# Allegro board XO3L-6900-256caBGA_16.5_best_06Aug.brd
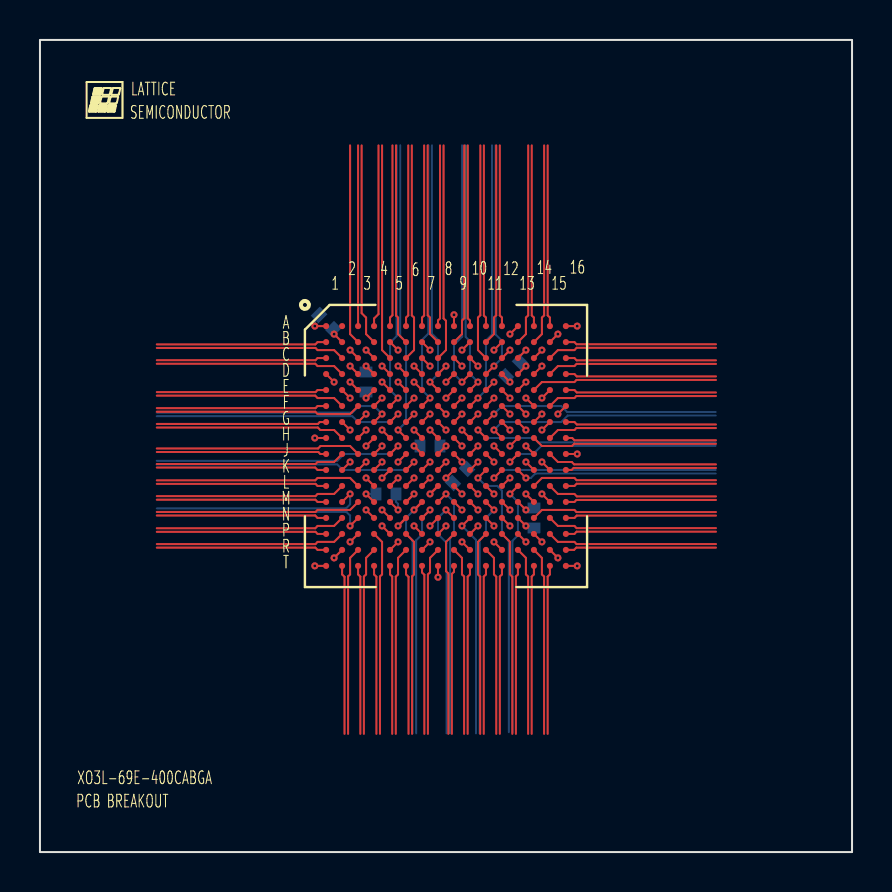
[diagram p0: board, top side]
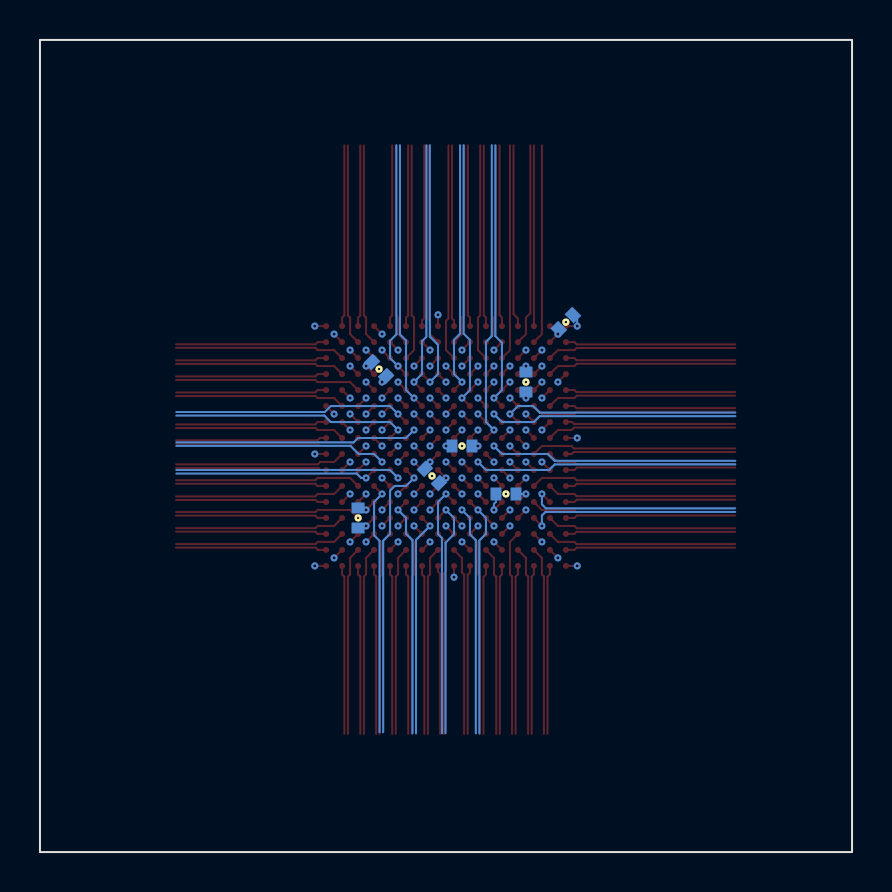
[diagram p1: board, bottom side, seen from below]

Outline 40.64 x 40.64 mm; copper layers: TOP, L2_GND, L3_SIGNAL, L4_SIGNAL, L5_PWR, BOTTOM. Coordinates in mm from the lower left corner of the outline.
Outline path: rectangle 0,0 40.64,40.64

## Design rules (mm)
net group CDPB4: nets PB4C PB4D
net group CDPB13: nets PB13C PB13D
net group CDPB18: nets PB18C PB18D
net group CDPB26: nets PB26C PB26D
net group CDPB31: nets PB31C PB31D
net group CDPB38: nets PB38C PB38D
net group CDPL2: nets PL2C PL2D
net group CDPL4: nets PL4C PL4D
net group CDPL6: nets PL6C PL6D
net group CDPL7: nets PL7C PL7D
net group CDPL9: nets PL9C PL9D
net group CDPL10: nets PL10C PL10D
net group CDPL15: nets PL15C PL15D
net group CDPL16: nets PL16C PL16D
net group CDPL19: nets PL19C PL19D
net group CDPL21: nets PL21C PL21D
net group CDPL23: nets PL23C PL23D
net group CDPL25: nets PL25C PL25D
net group CDPR2: nets PR2C PR2D
net group CDPR4: nets PR4C PR4D
net group CDPR6: nets PR6C PR6D
net group CDPR7: nets PR7C PR7D
net group CDPR10: nets PR10C PR10D
net group CDPR11: nets PR11C PR11D
net group CDPR16: nets PR16C PR16D
net group CDPR17: nets PR17C PR17D
net group CDPR19: nets PR19C PR19D
net group CDPR21: nets PR21C PR21D
net group CDPR23: nets PR23C PR23D
net group CDPR25: nets PR25C PR25D
net group CDPT14: nets PT14C PT14D
net group CDPT17: nets PT17C PT17D
net group CDPT22: nets PT22C PT22D
net group CDPT27: nets PT27C PT27D
net group CDPT36: nets PT36C PT36D
net group PB4: nets PB4A PB4B
net group PB6: nets PB6A PB6B
net group PB7: nets PB7A PB7B
net group PB9: nets PB9A PB9B
net group PB10: nets PB10A PB10B
net group PB12: nets PB12A PB12B
net group PB13: nets PB13A PB13B
net group PB15: nets PB15A PB15B
net group PB16: nets PB16A PB16B
net group PB18: nets PB18A PB18B
net group PB21: nets PB21A PB21B
net group PB23: nets PB23A PB23B
net group PB26: nets PB26A PB26B
net group PB28: nets PB28A PB28B
net group PB29: nets PB29A PB29B
net group PB31: nets PB31A PB31B
net group PB34: nets PB34A PB34B
net group PB35: nets PB35A PB35B
net group PB37: nets PB37A PB37B
net group PB38: nets PB38A PB38B
net group PL3: nets PL3A PL3B
net group PL4: nets PL4A PL4B
net group PL6: nets PL6A PL6B
net group PL8: nets PL8A PL8B
net group PL9: nets PL9A PL9B
net group PL10: nets PL10A PL10B
net group PL11: nets PL11A PL11B
net group PL12: nets PL12A PL12B
net group PL15: nets PL15A PL15B
net group PL17: nets PL17A PL17B
net group PL19: nets PL19A PL19B
net group PL22: nets PL22A PL22B
net group PL24: nets PL24A PL24B
net group PL25: nets PL25A PL25B
net group PR2: nets PR2A PR2B
net group PR3: nets PR3A PR3B
net group PR5: nets PR5A PR5B
net group PR7: nets PR7A PR7B
net group PR9: nets PR9A PR9B
net group PR11: nets PR11A PR11B
net group PR12: nets PR12A PR12B
net group PR15: nets PR15A PR15B
net group PR16: nets PR16A PR16B
net group PR17: nets PR17A PR17B
net group PR18: nets PR18A PR18B
net group PR21: nets PR21A PR21B
net group PR23: nets PR23A PR23B
net group PR24: nets PR24A PR24B
net group PT9: nets PT9A PT9B
net group PT10: nets PT10A PT10B
net group PT11: nets PT11A PT11B
net group PT12: nets PT12A PT12B
net group PT14: nets PT14A PT14B
net group PT15: nets PT15A PT15B
net group PT16: nets PT16A PT16B
net group PT17: nets PT17A PT17B
net group PT18: nets PT18A PT18B
net group PT21: nets PT21A PT21B
net group PT22: nets PT22A PT22B
net group PT25: nets PT25A PT25B
net group PT26: nets PT26A PT26B
net group PT27: nets PT27A PT27B
net group PT28: nets PT28A PT28B
net group PT32: nets PT32A PT32B
net group PT33: nets PT33A PT33B
net group PT34: nets PT34A PT34B
net group PT35: nets PT35A PT35B
net group PT36: nets PT36A PT36B

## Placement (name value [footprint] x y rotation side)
BGA  -  [BGA256C80P16X16_1400X1400X17-1]  20.32 20.32 270 top
C1  VAL  [C0402]  16.32 23.52 90 bottom
C2  VAL  [C0402]  23.67 24.17 45 bottom
C3  VAL  [C0402]  14.32 26.52 315 bottom
C4  VAL  [C0402]  19.52 20.32 0 bottom
C5  VAL  [C0402]  24.72 16.72 270 bottom
C6  VAL  [C0402]  21.02 18.82 45 bottom
C7  VAL  [C0402]  17.32 17.92 0 bottom
NOREF  -  []  24.69 13 0 top

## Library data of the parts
BGA = BGA256C80P16X16_1400X1400X17-1
C1-C7 = C0402: User Part Number: UPN; Tolerance: TOL

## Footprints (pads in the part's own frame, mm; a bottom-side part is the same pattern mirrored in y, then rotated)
BGA256C80P16X16_1400X1400X17-1
  round 0.305 smd: A1(-6,-6) A2(-6,-5.2) A3(-6,-4.4) A4(-6,-3.6) A5(-6,-2.8) A6(-6,-2) A7(-6,-1.2) A8(-6,-0.4) A9(-6,0.4) A10(-6,1.2) A11(-6,2) A12(-6,2.8) A13(-6,3.6) A14(-6,4.4) A15(-6,5.2) A16(-6,6) B1(-5.2,-6) B2(-5.2,-5.2) B3(-5.2,-4.4) B4(-5.2,-3.6) B5(-5.2,-2.8) B6(-5.2,-2) B7(-5.2,-1.2) B8(-5.2,-0.4) B9(-5.2,0.4) B10(-5.2,1.2) B11(-5.2,2) B12(-5.2,2.8) B13(-5.2,3.6) B14(-5.2,4.4) B15(-5.2,5.2) B16(-5.2,6) C1(-4.4,-6) C2(-4.4,-5.2) C3(-4.4,-4.4) C4(-4.4,-3.6) C5(-4.4,-2.8) C6(-4.4,-2) C7(-4.4,-1.2) C8(-4.4,-0.4) C9(-4.4,0.4) C10(-4.4,1.2) C11(-4.4,2) C12(-4.4,2.8) C13(-4.4,3.6) C14(-4.4,4.4) C15(-4.4,5.2) C16(-4.4,6) D1(-3.6,-6) D2(-3.6,-5.2) D3(-3.6,-4.4) D4(-3.6,-3.6) D5(-3.6,-2.8) D6(-3.6,-2) D7(-3.6,-1.2) D8(-3.6,-0.4) D9(-3.6,0.4) D10(-3.6,1.2) D11(-3.6,2) D12(-3.6,2.8) D13(-3.6,3.6) D14(-3.6,4.4) D15(-3.6,5.2) D16(-3.6,6) E1(-2.8,-6) E2(-2.8,-5.2) E3(-2.8,-4.4) E4(-2.8,-3.6) E5(-2.8,-2.8) E6(-2.8,-2) E7(-2.8,-1.2) E8(-2.8,-0.4) E9(-2.8,0.4) E10(-2.8,1.2) E11(-2.8,2) E12(-2.8,2.8) E13(-2.8,3.6) E14(-2.8,4.4) E15(-2.8,5.2) E16(-2.8,6) F1(-2,-6) F2(-2,-5.2) F3(-2,-4.4) F4(-2,-3.6) F5(-2,-2.8) F6(-2,-2) F7(-2,-1.2) F8(-2,-0.4) F9(-2,0.4) F10(-2,1.2) F11(-2,2) F12(-2,2.8) F13(-2,3.6) F14(-2,4.4) F15(-2,5.2) F16(-2,6) G1(-1.2,-6) G2(-1.2,-5.2) G3(-1.2,-4.4) G4(-1.2,-3.6) G5(-1.2,-2.8) G6(-1.2,-2) G7(-1.2,-1.2) G8(-1.2,-0.4) G9(-1.2,0.4) G10(-1.2,1.2) G11(-1.2,2) G12(-1.2,2.8) G13(-1.2,3.6) G14(-1.2,4.4) G15(-1.2,5.2) G16(-1.2,6) H1(-0.4,-6) H2(-0.4,-5.2) H3(-0.4,-4.4) H4(-0.4,-3.6) H5(-0.4,-2.8) H6(-0.4,-2) H7(-0.4,-1.2) H8(-0.4,-0.4) H9(-0.4,0.4) H10(-0.4,1.2) H11(-0.4,2) H12(-0.4,2.8) H13(-0.4,3.6) H14(-0.4,4.4) H15(-0.4,5.2) H16(-0.4,6) J1(0.4,-6) J2(0.4,-5.2) J3(0.4,-4.4) J4(0.4,-3.6) J5(0.4,-2.8) J6(0.4,-2) J7(0.4,-1.2) J8(0.4,-0.4) J9(0.4,0.4) J10(0.4,1.2) J11(0.4,2) J12(0.4,2.8) J13(0.4,3.6) J14(0.4,4.4) J15(0.4,5.2) J16(0.4,6) K1(1.2,-6) K2(1.2,-5.2) K3(1.2,-4.4) K4(1.2,-3.6) K5(1.2,-2.8) K6(1.2,-2) K7(1.2,-1.2) K8(1.2,-0.4) K9(1.2,0.4) K10(1.2,1.2) K11(1.2,2) K12(1.2,2.8) K13(1.2,3.6) K14(1.2,4.4) K15(1.2,5.2) K16(1.2,6) L1(2,-6) L2(2,-5.2) L3(2,-4.4) L4(2,-3.6) L5(2,-2.8) L6(2,-2) L7(2,-1.2) L8(2,-0.4) L9(2,0.4) L10(2,1.2) L11(2,2) L12(2,2.8) L13(2,3.6) L14(2,4.4) L15(2,5.2) L16(2,6) M1(2.8,-6) M2(2.8,-5.2) M3(2.8,-4.4) M4(2.8,-3.6) M5(2.8,-2.8) M6(2.8,-2) M7(2.8,-1.2) M8(2.8,-0.4) M9(2.8,0.4) M10(2.8,1.2) M11(2.8,2) M12(2.8,2.8) M13(2.8,3.6) M14(2.8,4.4) M15(2.8,5.2) M16(2.8,6) N1(3.6,-6) N2(3.6,-5.2) N3(3.6,-4.4) N4(3.6,-3.6) N5(3.6,-2.8) N6(3.6,-2) N7(3.6,-1.2) N8(3.6,-0.4) N9(3.6,0.4) N10(3.6,1.2) N11(3.6,2) N12(3.6,2.8) N13(3.6,3.6) N14(3.6,4.4) N15(3.6,5.2) N16(3.6,6) P1(4.4,-6) P2(4.4,-5.2) P3(4.4,-4.4) P4(4.4,-3.6) P5(4.4,-2.8) P6(4.4,-2) P7(4.4,-1.2) P8(4.4,-0.4) P9(4.4,0.4) P10(4.4,1.2) P11(4.4,2) P12(4.4,2.8) P13(4.4,3.6) P14(4.4,4.4) P15(4.4,5.2) P16(4.4,6) R1(5.2,-6) R2(5.2,-5.2) R3(5.2,-4.4) R4(5.2,-3.6) R5(5.2,-2.8) R6(5.2,-2) R7(5.2,-1.2) R8(5.2,-0.4) R9(5.2,0.4) R10(5.2,1.2) R11(5.2,2) R12(5.2,2.8) R13(5.2,3.6) R14(5.2,4.4) R15(5.2,5.2) R16(5.2,6) T1(6,-6) T2(6,-5.2) T3(6,-4.4) T4(6,-3.6) T5(6,-2.8) T6(6,-2) T7(6,-1.2) T8(6,-0.4) T9(6,0.4) T10(6,1.2) T11(6,2) T12(6,2.8) T13(6,3.6) T14(6,4.4) T15(6,5.2) T16(6,6)
C0402
  rect 0.54x0.64 smd: 1(-0.5,0) 2(0.5,0)

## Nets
GND: BGA.B2 BGA.B15 BGA.C3 BGA.C14 BGA.D4 BGA.D13 BGA.E5 BGA.E12 BGA.F6 BGA.F11 BGA.H8 BGA.H9 BGA.J8 BGA.J9 BGA.L6 BGA.L11 BGA.M5 BGA.M12 BGA.N4 BGA.N13 BGA.P3 BGA.P14 BGA.R2 BGA.R15 C1.2 C2.2 C3.2 C4.2 C5.2 C6.2 C7.2
VCC: BGA.A1 BGA.A16 BGA.G7 BGA.G10 BGA.K7 BGA.K10 BGA.T1 BGA.T16 C3.1
VCCIO0: BGA.D5 BGA.D12 BGA.G8 BGA.G9 C2.1
VCCIO1: BGA.E13 BGA.H10 BGA.J10 BGA.M13 C5.1
VCCIO2: BGA.K8 BGA.K9 BGA.N5 BGA.N12 C6.1
VCCIO3: BGA.M4 C7.1
VCCIO4: BGA.H7 BGA.J7 C4.1
VCCIO5: BGA.E4 C1.1
NC: BGA.A2
PB4A: BGA.P4
PB4B: BGA.T4
PB4C: BGA.T2
PB4D: BGA.R3
PB6A: BGA.R5
PB6B: BGA.P5
PB7A: BGA.T3
PB7B: BGA.R4
PB9A: BGA.T5
PB9B: BGA.R6
PB10A: BGA.N6
PB10B: BGA.L7
PB12A: BGA.P6
PB12B: BGA.T6
PB13A: BGA.R7
PB13B: BGA.P7
PB13C: BGA.M7
PB13D: BGA.N7
PB15A: BGA.M6
PB15B: BGA.L8
PB16A: BGA.T7
PB16B: BGA.R8
PB18A: BGA.P8
PB18B: BGA.T8
PB18C: BGA.N8
PB18D: BGA.L9
PB21A: BGA.M8
PB21B: BGA.N9
PB23A: BGA.T9
PB23B: BGA.P9
PB26A: BGA.R9
PB26B: BGA.T10
PB26C: BGA.M9
PB26D: BGA.L10
PB28A: BGA.N10
PB28B: BGA.M11
PB29A: BGA.P10
PB29B: BGA.R10
PB31A: BGA.T11
PB31B: BGA.P11
PB31C: BGA.M10
PB31D: BGA.N11
PB34A: BGA.R13
PB34B: BGA.T14
PB35A: BGA.R11
PB35B: BGA.T12
PB37A: BGA.P12
PB37B: BGA.T13
PB38A: BGA.R12
PB38B: BGA.P13
PB38C: BGA.T15
PB38D: BGA.R14
PL2C: BGA.B1
PL2D: BGA.C2
PL3A: BGA.D3
PL3B: BGA.D1
PL4A: BGA.E2
PL4B: BGA.E3
PL4C: BGA.C1
PL4D: BGA.D2
PL6A: BGA.E1
PL6B: BGA.F2
PL6C: BGA.F4
PL6D: BGA.G6
PL7C: BGA.G5
PL7D: BGA.G4
PL8A: BGA.F3
PL8B: BGA.F1
PL9A: BGA.G2
PL9B: BGA.G3
PL9C: BGA.F5
PL9D: BGA.H6
PL10A: BGA.G1
PL10B: BGA.H2
PL10C: BGA.H4
PL10D: BGA.J6
PL11A: BGA.H3
PL11B: BGA.H1
PL12A: BGA.J1
PL12B: BGA.J3
PL15A: BGA.J2
PL15B: BGA.K1
PL15C: BGA.H5
PL15D: BGA.J4
PL16C: BGA.J5
PL16D: BGA.K6
PL17A: BGA.K3
PL17B: BGA.K2
PL19A: BGA.L1
PL19B: BGA.L3
PL19C: BGA.K4
PL19D: BGA.L5
PL21C: BGA.K5
PL21D: BGA.L4
PL22A: BGA.L2
PL22B: BGA.M1
PL23C: BGA.N2
PL23D: BGA.P1
PL24A: BGA.M3
PL24B: BGA.N1
PL25A: BGA.M2
PL25B: BGA.N3
PL25C: BGA.R1
PL25D: BGA.P2
PR2A: BGA.D14
PR2B: BGA.E15
PR2C: BGA.C15
PR2D: BGA.B16
PR3A: BGA.D16
PR3B: BGA.E14
PR4C: BGA.C16
PR4D: BGA.D15
PR5A: BGA.E16
PR5B: BGA.F15
PR6C: BGA.F13
PR6D: BGA.G12
PR7A: BGA.F14
PR7B: BGA.F16
PR7C: BGA.F12
PR7D: BGA.G13
PR9A: BGA.G15
PR9B: BGA.G14
PR10C: BGA.G11
PR10D: BGA.H12
PR11A: BGA.G16
PR11B: BGA.H15
PR11C: BGA.H13
PR11D: BGA.J12
PR12A: BGA.H14
PR12B: BGA.H16
PR15A: BGA.J16
PR15B: BGA.J14
PR16A: BGA.J15
PR16B: BGA.K16
PR16C: BGA.H11
PR16D: BGA.J13
PR17A: BGA.K14
PR17B: BGA.K15
PR17C: BGA.J11
PR17D: BGA.L12
PR18A: BGA.L16
PR18B: BGA.L14
PR19C: BGA.K13
PR19D: BGA.K12
PR21A: BGA.L15
PR21B: BGA.M16
PR21C: BGA.K11
PR21D: BGA.L13
PR23A: BGA.M14
PR23B: BGA.M15
PR23C: BGA.N15
PR23D: BGA.P16
PR24A: BGA.N16
PR24B: BGA.N14
PR25C: BGA.P15
PR25D: BGA.R16
PT9A: BGA.C4
PT9B: BGA.B5
PT9C: BGA.B3
PT10A: BGA.A4
PT10B: BGA.C5
PT11A: BGA.A5
PT11B: BGA.B6
PT12A: BGA.A3
PT12B: BGA.B4
PT14A: BGA.D6
PT14B: BGA.E7
PT14C: BGA.C6
PT14D: BGA.A6
PT15A: BGA.B7
PT15B: BGA.C7
PT16A: BGA.E6
PT16B: BGA.D7
PT17A: BGA.F7
PT17B: BGA.E8
PT17C: BGA.A7
PT17D: BGA.B8
PT18A: BGA.C8
PT18B: BGA.A8
PT21A: BGA.D8
PT21B: BGA.E9
PT22A: BGA.F8
PT22B: BGA.D9
PT22C: BGA.A9
PT22D: BGA.C9
PT25A: BGA.B9
PT25B: BGA.A10
PT26A: BGA.F9
PT26B: BGA.E11
PT27A: BGA.D10
PT27B: BGA.E10
PT27C: BGA.C10
PT27D: BGA.B10
PT28A: BGA.A11
PT28B: BGA.C11
PT32A: BGA.F10
PT32B: BGA.D11
PT33A: BGA.B11
PT33B: BGA.A12
PT34A: BGA.B13
PT34B: BGA.A14
PT35A: BGA.C12
PT35B: BGA.B12
PT36A: BGA.B14
PT36B: BGA.A15
PT36C: BGA.A13
PT36D: BGA.C13

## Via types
v1: diameter 0.356, hole 0.152, TOP to BOTTOM, 158 vias

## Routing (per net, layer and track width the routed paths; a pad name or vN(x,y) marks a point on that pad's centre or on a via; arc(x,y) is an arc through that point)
GND: length 16.6
  TOP w0.102: v1(18.72,22.72) BGA.F6 ; v1(24.32,16.32) BGA.N13 ; v1(20.32,20.32) BGA.J8 ; v1(23.52,22.72) BGA.E12 ; v1(15.52,15.52) BGA.P3 ; v1(23.52,17.12) BGA.M12 ; v1(19.52,21.12) BGA.H8 ; v1(22.72,22.72) BGA.F11 ; v1(25.92,14.72) BGA.R15 ; v1(21.12,19.52) BGA.J9 ; v1(15.52,25.12) BGA.C3 ; v1(16.32,24.32) BGA.D4 ; v1(25.12,25.12) BGA.C14 ; v1(18.72,18.72) BGA.L6 ; v1(17.12,23.52) BGA.E5 ; v1(25.92,25.92) BGA.B15 ; v1(22.72,17.92) BGA.L11 ; v1(14.72,25.92) BGA.B2 ; v1(16.32,17.12) BGA.N4 ; v1(24.32,24.32) BGA.D13 ; BGA.M5 v1(17.92,17.12) ; v1(21.12,20.32) BGA.H9 ; v1(14.72,14.72) BGA.R2 ; v1(25.12,15.52) BGA.P14
  BOTTOM w0.102: C5.2 24.62,16.32 v1(24.32,16.32) ; C2.2 24.12,24.52 v1(24.32,24.32) ; C6.2 21.37,19.27 v1(21.12,19.52) ; C1.2 v1(16.32,24.32) ; C7.2 17.82,17.52 17.92,17.43 v1(17.92,17.12) ; C3.2 14.72,26.12 v1(14.72,25.92) ; C4.2 v1(20.32,20.32)
VCC: length 5.2
  TOP w0.102: v1(19.52,21.92) BGA.G7 ; v1(13.75,26.32) BGA.A1 ; v1(26.89,26.32) BGA.A16 ; v1(19.52,19.52) BGA.K7 ; v1(21.92,21.92) BGA.G10 ; v1(21.92,19.52) BGA.K10 ; v1(26.89,14.32) BGA.T16 ; v1(13.75,14.32) BGA.T1
  BOTTOM w0.102: C3.1 13.97,26.84 13.75,26.62 v1(13.75,26.32)
VCCIO0: length 2.6
  TOP w0.102: v1(21.12,21.92) BGA.G9 ; v1(17.12,24.32) BGA.D5 ; v1(23.52,23.52) BGA.D12 ; v1(20.32,21.12) BGA.G8
  BOTTOM w0.102: C2.1 23.32,23.72 v1(23.52,23.52)
VCCIO1: length 2.7
  TOP w0.102: v1(24.32,23.52) BGA.E13 ; v1(21.12,21.12) BGA.H10 ; v1(21.92,20.32) BGA.J10 ; v1(24.32,17.12) BGA.M13
  BOTTOM w0.102: v1(24.32,17.12) 24.66,17.12 24.72,17.18 C5.1
VCCIO2: length 2.7
  TOP w0.102: v1(23.52,16.32) BGA.N12 ; v1(17.12,17.12) BGA.N5 ; BGA.K9 v1(20.32,18.72) ; v1(20.32,19.52) BGA.K8
  BOTTOM w0.102: C6.1 20.57,18.47 v1(20.32,18.72)
VCCIO3: length 1.1
  TOP w0.102: BGA.M4 v1(16.32,17.92)
  BOTTOM w0.102: v1(16.32,17.92) C7.1
VCCIO4: length 1.4
  TOP w0.102: v1(18.72,20.32) BGA.J7 ; v1(18.72,21.12) BGA.H7
  BOTTOM w0.102: C4.1 v1(18.72,20.32)
VCCIO5: length 0.9
  TOP w0.102: v1(16.32,22.72) BGA.E4
  BOTTOM w0.102: C1.1 v1(16.32,22.72)
PB4A: length 10.2
  TOP w0.102: BGA.P4 17.12,15.52 17.12,13.89 17.01,13.79 17.01,5.92
PB4B: length 8.5
  TOP w0.102: BGA.T4 16.72,13.89 16.84,13.78 16.84,5.92
PB4C: length 8.5
  TOP w0.102: 15.24,5.92 15.24,13.77 15.12,13.89 BGA.T2
PB4D: length 9.4
  TOP w0.102: BGA.R3 15.52,14.72 15.52,13.89 15.42,13.79 15.42,5.92
PB6A: length 11
  TOP w0.102: v1(17.92,15.52) BGA.R5
  L3_SIGNAL w0.102: v1(17.92,15.52) 17.65,15.79 17.51,15.79 17.25,15.52 17.25,5.95
PB6B: length 11.2
  TOP w0.102: v1(17.12,16.32) BGA.P5
  L3_SIGNAL w0.102: v1(17.12,16.32) 17.39,16.05 17.39,15.91 17.31,15.84 17.07,15.6 17.07,5.95
PB7A: length 8.4
  TOP w0.102: BGA.T3 15.92,13.89 16.03,13.78 16.03,5.92
PB7B: length 9.4
  TOP w0.102: 16.21,5.92 16.21,13.78 16.32,13.89 16.32,14.72 BGA.R4
PB9A: length 8.4
  TOP w0.102: 17.63,5.92 17.63,13.79 17.52,13.89 BGA.T5
PB9B: length 9.4
  TOP w0.102: BGA.R6 17.92,14.72 17.92,13.89 17.81,13.78 17.81,5.92
PB10A: length 1.1
  TOP w0.102: v1(17.92,16.32) BGA.N6 v1(17.92,16.32)
PB10B: length 0.6
  TOP w0.102: v1(19.52,18.72) BGA.L7
PB12A: length 10.2
  TOP w0.102: BGA.P6 18.72,15.52 18.72,13.89 18.62,13.8 18.62,5.92
PB12B: length 8.5
  TOP w0.102: 18.45,5.92 18.45,13.77 18.32,13.89 BGA.T6
PB13A: length 11
  TOP w0.102: v1(19.52,15.52) BGA.R7
  L3_SIGNAL w0.102: 18.73,5.95 18.73,15.42 19.03,15.72 19.32,15.72 v1(19.52,15.52)
PB13B: length 11.2
  TOP w0.102: v1(18.72,16.32) BGA.P7
  L3_SIGNAL w0.102: v1(18.72,16.32) 18.92,16.12 18.92,15.86 18.56,15.5 18.56,5.95
PB13C: length 25.8
  TOP w0.102: v1(18.72,17.12) BGA.M7 v1(18.72,17.12)
  L3_SIGNAL w0.102: v1(18.72,17.12) 18.32,16.72 15.95,16.72 15.65,17.02 5.85,17.02
  BOTTOM w0.102: v1(18.72,17.12) 18.32,16.72 18.32,15.92 18.65,15.59 18.65,5.94
PB13D: length 26
  TOP w0.102: v1(19.52,17.12) BGA.N7
  L3_SIGNAL w0.102: 5.85,17.2 15.65,17.2 15.97,17.52 19.12,17.52 v1(19.52,17.12)
  BOTTOM w0.102: 18.83,5.94 18.83,15.6 19.12,15.9 BGA.N7 v1(19.52,17.12)
PB15A: length 1.1
  TOP w0.102: v1(18.72,17.92) BGA.M6 v1(18.72,17.92)
PB15B: length 1.1
  TOP w0.102: v1(19.52,17.92) BGA.L8 v1(19.52,17.92)
PB16A: length 8.5
  TOP w0.102: BGA.T7 19.12,13.99 19.24,13.87 19.24,5.92
PB16B: length 9.4
  TOP w0.102: BGA.R8 19.52,14.72 19.52,14 19.41,13.89 19.41,5.92
PB18A: length 11.6
  TOP w0.102: v1(20.32,16.32) BGA.P8
  L3_SIGNAL w0.102: 21.15,5.95 21.15,14.68 20.73,15.09 20.33,15.09 20.23,15.11 20.15,15.23 v1(20.32,16.32)
PB18B: length 11.4
  TOP w0.102: v1(19.92,13.75) BGA.T8
  L3_SIGNAL w0.102: 20.97,5.95 20.97,14.6 20.66,14.92 20.32,14.92 20.21,14.93 20.09,14.85 v1(19.92,13.75)
PB18C: length 11.2
  TOP w0.102: v1(19.52,16.32) BGA.N8
  L4_SIGNAL w0.102: v1(19.52,16.32) 19.03,15.83 19.03,14.91 19.3,14.64 19.3,5.96
PB18D: length 13.5
  TOP w0.102: v1(21.12,17.92) BGA.L9
  L4_SIGNAL w0.102: 19.48,5.96 19.48,14.64 19.92,15.08 19.92,17.29 20.15,17.52 20.72,17.52 v1(21.12,17.92)
PB21A: length 12.8
  TOP w0.102: v1(20.32,17.92) BGA.M8
  BOTTOM w0.102: v1(20.32,17.92) 20.72,17.52 20.72,15.91 20.52,15.71 20.52,5.94
PB21B: length 12.1
  TOP w0.102: v1(20.32,17.12) BGA.N9
  BOTTOM w0.102: v1(20.32,17.12) 19.92,16.72 19.92,15.9 20.35,15.48 20.35,5.94
PB23A: length 8.4
  TOP w0.102: BGA.T9 20.72,14.02 20.61,13.92 20.61,5.92
PB23B: length 10.2
  TOP w0.102: BGA.P9 20.32,15.52 20.32,14.05 20.44,13.94 20.44,5.92
PB26A: length 9.4
  TOP w0.102: BGA.R9 21.12,14.72 21.12,13.89 21.23,13.79 21.23,5.92
PB26B: length 8.5
  TOP w0.102: BGA.T10 21.52,13.89 21.4,13.78 21.4,5.92
PB26C: length 12
  TOP w0.102: v1(21.12,17.12) BGA.M9
  L4_SIGNAL w0.102: 21.06,5.95 21.06,14.8 20.72,15.14 20.72,16.72 v1(21.12,17.12)
PB26D: length 12.8
  TOP w0.102: v1(21.92,17.92) BGA.L10
  L4_SIGNAL w0.102: 21.24,5.95 21.24,14.8 21.52,15.09 21.52,17.52 v1(21.92,17.92)
PB28A: length 11.2
  TOP w0.102: v1(21.12,16.32) BGA.N10
  BOTTOM w0.102: 21.82,5.94 21.82,15.62 v1(21.12,16.32)
PB28B: length 12
  TOP w0.102: v1(22.72,17.12) BGA.M11
  BOTTOM w0.102: v1(22.72,17.12) 22.32,16.72 22.32,15.93 22,15.61 22,5.94
PB29A: length 11.1
  TOP w0.102: v1(21.92,16.32) BGA.P10
  L3_SIGNAL w0.102: v1(21.92,16.32) 21.72,16.12 21.72,15.85 22.03,15.53 22.03,5.95
PB29B: length 11
  TOP w0.102: v1(21.12,15.52) BGA.R10
  L3_SIGNAL w0.102: 21.85,5.95 21.85,15.46 21.59,15.72 21.32,15.72 v1(21.12,15.52)
PB31A: length 8.4
  TOP w0.102: BGA.T11 22.32,13.89 22.21,13.78 22.21,5.92
PB31B: length 10.2
  TOP w0.102: 22.03,5.92 22.03,13.78 21.92,13.89 21.92,15.52 BGA.P11
PB31C: length 12
  TOP w0.102: v1(21.92,17.12) BGA.M10
  L4_SIGNAL w0.102: 22.63,5.96 22.63,14.9 22.32,15.21 22.32,16.72 v1(21.92,17.12)
PB31D: length 11.2
  TOP w0.102: v1(22.72,16.32) BGA.N11
  L4_SIGNAL w0.102: v1(22.72,16.32) 23.13,15.91 23.13,15.23 22.81,14.9 22.81,5.96
PB34A: length 9.4
  TOP w0.102: BGA.R13 24.32,14.72 24.32,13.89 24.43,13.78 24.43,5.92
PB34B: length 8.4
  TOP w0.102: BGA.T14 24.72,13.89 24.61,13.78 24.61,5.92
PB35A: length 9.4
  TOP w0.102: 22.84,5.92 22.84,13.78 22.72,13.89 22.72,14.72 BGA.R11
PB35B: length 8.4
  TOP w0.102: 23.01,5.92 23.01,13.79 23.12,13.89 BGA.T12
PB37A: length 10.2
  TOP w0.102: BGA.P12 23.52,15.52 23.52,13.89 23.64,13.77 23.64,5.92
PB37B: length 8.4
  TOP w0.102: BGA.T13 23.92,13.89 23.82,13.79 23.82,5.92
PB38A: length 10.7
  TOP w0.102: v1(22.72,15.52) BGA.R12
  L3_SIGNAL w0.102: v1(22.72,15.52) 23.24,15.52 23.44,15.32 23.44,5.95
PB38B: length 10.7
  TOP w0.102: v1(24.32,15.52) BGA.P13
  L3_SIGNAL w0.102: v1(24.32,15.52) 23.8,15.52 23.62,15.34 23.62,5.95
PB38C: length 8.4
  TOP w0.102: BGA.T15 25.52,13.89 25.41,13.78 25.41,5.92
PB38D: length 9.4
  TOP w0.102: 25.23,5.92 25.23,13.79 25.12,13.89 25.12,14.72 BGA.R14
PL2C: length 8.5
  TOP w0.102: BGA.B1 13.89,25.52 13.78,25.41 5.85,25.41
PL2D: length 9.5
  TOP w0.102: BGA.C2 14.72,25.12 13.89,25.12 13.79,25.23 5.85,25.23
PL3A: length 10.4
  TOP w0.102: v1(15.52,24.32) BGA.D3
  L3_SIGNAL w0.102: v1(15.52,24.32) 15.25,24.05 15.11,24.05 14.82,24.35 5.9,24.35
PL3B: length 10.3
  TOP w0.102: v1(14.72,23.52) BGA.D1
  L3_SIGNAL w0.102: v1(14.72,23.52) 14.99,23.79 14.99,23.93 14.75,24.17 5.9,24.17
PL4A: length 10.5
  TOP w0.102: v1(15.52,22.72) BGA.E2
  L3_SIGNAL w0.102: 5.87,22.87 15,22.87 15.16,23.03 15.42,23.03 15.52,22.93 v1(15.52,22.72)
PL4B: length 10.5
  TOP w0.102: v1(15.52,23.52) BGA.E3
  L3_SIGNAL w0.102: 5.87,23.05 14.92,23.05 15.08,23.21 15.32,23.21 15.42,23.21 15.52,23.31 v1(15.52,23.52)
PL4C: length 8.5
  TOP w0.102: 5.85,24.61 13.79,24.61 13.89,24.72 BGA.C1
PL4D: length 9.5
  TOP w0.102: BGA.D2 14.72,24.32 13.89,24.32 13.78,24.44 5.85,24.44
PL6A: length 8.5
  TOP w0.102: 5.85,23.02 13.79,23.02 13.89,23.12 BGA.E1
PL6B: length 9.5
  TOP w0.102: 5.85,22.84 13.77,22.84 13.89,22.72 14.72,22.72 BGA.F2
PL6C: length 12.1
  TOP w0.102: v1(17.12,22.72) BGA.F4
  L4_SIGNAL w0.102: v1(17.12,22.72) 16.72,23.12 15.15,23.12 14.83,22.8 5.85,22.8
PL6D: length 13.7
  TOP w0.102: v1(18.72,21.92) BGA.G6
  L4_SIGNAL w0.102: v1(18.72,21.92) 18.32,22.32 15.13,22.32 14.83,22.63 5.85,22.63
PL7C: length 12.9
  TOP w0.102: v1(17.92,21.92) BGA.G5
  BOTTOM w0.102: 5.84,21.81 15.63,21.81 15.92,21.52 BGA.G5 v1(17.92,21.92)
PL7D: length 12.1
  TOP w0.102: v1(17.12,21.92) BGA.G4
  BOTTOM w0.102: v1(17.12,21.92) 16.72,22.32 15.96,22.32 15.63,21.99 5.84,21.99
PL8A: length 10.3
  TOP w0.102: 5.85,22.04 13.78,22.04 13.89,21.92 15.52,21.92 BGA.F3
PL8B: length 8.5
  TOP w0.102: 5.85,22.21 13.79,22.21 13.89,22.32 BGA.F1
PL9A: length 11.1
  TOP w0.102: v1(15.52,21.12) BGA.G2
  L3_SIGNAL w0.102: v1(15.52,21.12) 15.72,21.32 15.72,21.61 15.54,21.79 5.85,21.79
PL9B: length 11.2
  TOP w0.102: v1(16.32,21.92) BGA.G3
  L3_SIGNAL w0.102: v1(16.32,21.92) 16.12,21.72 15.86,21.72 15.61,21.97 5.85,21.97
PL9C: length 13.5
  TOP w0.102: v1(17.92,22.72) BGA.F5
  BOTTOM w0.102: 17.85,35.37 17.85,25.82 17.52,25.49 17.52,23.12 v1(17.92,22.72)
PL9D: length 15.1
  TOP w0.102: v1(17.92,21.12) BGA.H6
  BOTTOM w0.102: v1(17.92,21.12) 18.32,21.52 18.32,25.53 18.03,25.82 18.03,35.37
PL10A: length 8.5
  TOP w0.102: 5.85,21.42 13.91,21.42 14,21.52 BGA.G1
PL10B: length 9.5
  TOP w0.102: 5.85,21.24 13.91,21.24 14.03,21.12 14.72,21.12 BGA.H2
PL10C: length 11.1
  TOP w0.102: v1(16.32,20.32) BGA.H4
  L4_SIGNAL w0.102: v1(16.32,20.32) 15.89,20.32 15.67,20.1 5.85,20.1
PL10D: length 12.8
  TOP w0.102: v1(17.92,19.52) BGA.J6
  L4_SIGNAL w0.102: 5.85,19.92 17.29,19.92 17.69,19.52 v1(17.92,19.52)
PL11A: length 11.4
  TOP w0.102: v1(16.32,21.12) BGA.H3
  L3_SIGNAL w0.102: 5.85,21.12 13.92,21.12 14.32,21.12 14.75,20.69 15.89,20.69 v1(16.32,21.12)
PL11B: length 8.6
  TOP w0.102: v1(13.75,20.72) BGA.H1
  L3_SIGNAL w0.102: 5.85,20.94 13.53,20.94 v1(13.75,20.72)
PL12A: length 8.5
  TOP w0.102: BGA.J1 14.03,19.92 13.93,20.02 5.85,20.02
PL12B: length 10.3
  TOP w0.102: BGA.J3 15.52,20.32 14.04,20.32 13.92,20.2 5.85,20.2
PL15A: length 9.5
  TOP w0.102: 5.85,19.42 13.79,19.42 13.89,19.52 14.72,19.52 BGA.J2
PL15B: length 8.5
  TOP w0.102: BGA.K1 13.89,19.12 13.77,19.24 5.85,19.24
PL15C: length 12.1
  TOP w0.102: v1(17.12,21.12) BGA.H5
  L4_SIGNAL w0.102: 5.85,21.32 14.41,21.32 14.61,21.52 16.72,21.52 v1(17.12,21.12)
PL15D: length 12.2
  TOP w0.102: v1(17.12,20.32) BGA.J4
  L4_SIGNAL w0.102: 5.85,21.14 14.41,21.14 14.84,20.72 16.72,20.72 v1(17.12,20.32)
PL16C: length 13
  TOP w0.102: v1(17.92,20.32) BGA.J5
  BOTTOM w0.102: 5.84,19.58 14.88,19.58 15.22,19.92 BGA.J5 v1(17.92,20.32)
PL16D: length 13.7
  TOP w0.102: v1(18.72,19.52) BGA.K6
  BOTTOM w0.102: v1(18.72,19.52) BGA.K6 15.16,19.12 14.88,19.4 5.84,19.4
PL17A: length 11.2
  TOP w0.102: v1(16.32,19.52) BGA.K3
  L3_SIGNAL w0.102: 5.85,20 15.84,20 v1(16.32,19.52)
PL17B: length 10.4
  TOP w0.102: v1(15.52,19.52) BGA.K2
  L3_SIGNAL w0.102: 5.85,19.83 14.85,19.83 15.16,19.52 v1(15.52,19.52)
PL19A: length 8.5
  TOP w0.102: 5.85,18.42 13.79,18.42 13.89,18.32 BGA.L1
PL19B: length 10.3
  TOP w0.102: BGA.L3 15.52,18.72 13.89,18.72 13.78,18.6 5.85,18.6
PL19C: length 12.1
  TOP w0.102: v1(17.12,19.52) BGA.K4
  L4_SIGNAL w0.102: 5.84,18.8 15.67,18.8 16,19.12 16.27,19.12 BGA.K4 v1(17.12,19.52)
PL19D: length 12.9
  TOP w0.102: v1(17.92,18.72) BGA.L5
  L4_SIGNAL w0.102: 5.84,18.62 15.65,18.62 15.95,18.32 BGA.L5 v1(17.92,18.72)
PL21C: length 12.1
  TOP w0.102: v1(17.12,18.72) BGA.K5
  L3_SIGNAL w0.102: v1(17.12,18.72) 16.72,19.12 15.95,19.12 15.72,18.9 5.85,18.9
PL21D: length 11
  TOP w0.102: v1(16.32,18.72) BGA.L4
  L3_SIGNAL w0.102: v1(16.32,18.72) 5.88,18.72
PL22A: length 9.5
  TOP w0.102: BGA.L2 14.72,17.92 13.89,17.92 13.78,17.81 5.85,17.81
PL22B: length 8.5
  TOP w0.102: BGA.M1 13.89,17.52 13.78,17.63 5.85,17.63
PL23C: length 9.5
  TOP w0.102: 5.85,16.2 13.78,16.2 13.89,16.32 14.72,16.32 BGA.N2
PL23D: length 8.5
  TOP w0.102: 5.85,16.02 13.79,16.02 13.89,15.92 BGA.P1
PL24A: length 10.3
  TOP w0.102: 5.85,17.02 13.79,17.02 13.89,17.12 15.52,17.12 BGA.M3
PL24B: length 8.5
  TOP w0.102: 5.85,16.84 13.77,16.84 13.89,16.72 BGA.N1
PL25A: length 10.8
  TOP w0.102: v1(15.52,17.92) BGA.M2
  BOTTOM w0.102: v1(15.52,17.92) 15.52,17.4 15.32,17.2 5.85,17.2
PL25B: length 10.8
  TOP w0.102: v1(15.52,16.32) BGA.N3
  BOTTOM w0.102: 5.85,17.02 15.34,17.02 15.52,16.84 v1(15.52,16.32)
PL25C: length 8.5
  TOP w0.102: BGA.R1 13.89,15.12 13.78,15.23 5.85,15.23
PL25D: length 9.5
  TOP w0.102: BGA.P2 14.72,15.52 13.89,15.52 13.78,15.41 5.85,15.41
PR2A: length 9.9
  TOP w0.102: v1(25.12,24.32) BGA.D14
  L3_SIGNAL w0.102: v1(25.12,24.32) 25.12,23.8 25.31,23.61 33.83,23.61
PR2B: length 9.9
  TOP w0.102: v1(25.12,22.72) BGA.E15
  L3_SIGNAL w0.102: 33.83,23.43 25.31,23.43 25.12,23.24 v1(25.12,22.72)
PR2C: length 8.5
  TOP w0.102: BGA.C15 25.92,25.12 26.75,25.12 26.86,25.23 33.83,25.23
PR2D: length 7.6
  TOP w0.102: BGA.B16 26.75,25.52 26.85,25.41 33.83,25.41
PR3A: length 7.6
  TOP w0.102: BGA.D16 26.75,23.92 26.86,23.8 33.83,23.8
PR3B: length 9.3
  TOP w0.102: 33.83,23.63 26.85,23.63 26.75,23.52 25.12,23.52 BGA.E14
PR4C: length 7.6
  TOP w0.102: 33.83,24.61 26.86,24.61 26.75,24.72 BGA.C16
PR4D: length 8.5
  TOP w0.102: 33.83,24.43 26.86,24.43 26.75,24.32 25.92,24.32 BGA.D15
PR5A: length 7.6
  TOP w0.102: 33.83,23 26.87,23 26.75,23.12 BGA.E16
PR5B: length 8.5
  TOP w0.102: BGA.F15 25.92,22.72 26.75,22.72 26.85,22.82 33.83,22.82
PR6C: length 10.3
  TOP w0.102: v1(24.32,21.92) BGA.F13
  L4_SIGNAL w0.102: 33.82,22.48 25.94,22.48 25.78,22.32 24.95,22.32 24.55,21.92 v1(24.32,21.92)
PR6D: length 13.5
  TOP w0.102: v1(23.52,21.12) BGA.G12
  L4_SIGNAL w0.102: v1(23.52,21.12) BGA.G12 23.12,22.89 23.35,23.12 25.49,23.12 25.94,22.66 33.82,22.66
PR7A: length 10.3
  TOP w0.102: v1(24.32,22.72) BGA.F14
  L3_SIGNAL w0.102: v1(24.32,22.72) BGA.F14 26.24,22.32 26.31,22.25 33.82,22.25
PR7B: length 8.5
  TOP w0.102: v1(25.92,21.92) BGA.F16
  L3_SIGNAL w0.102: 33.82,22.07 26.42,22.07 26.27,21.92 v1(25.92,21.92)
PR7C: length 11.2
  TOP w0.102: v1(23.52,21.92) BGA.F12
  L4_SIGNAL w0.102: 33.82,21.22 25.79,21.22 25.49,21.52 23.92,21.52 v1(23.52,21.92)
PR7D: length 10.4
  TOP w0.102: v1(24.32,21.12) BGA.G13
  L4_SIGNAL w0.102: v1(24.32,21.12) 24.55,21.12 24.95,20.72 25.42,20.72 25.74,21.04 33.82,21.04
PR9A: length 9.6
  TOP w0.102: v1(25.12,21.12) BGA.G15
  L3_SIGNAL w0.102: 33.82,21.28 25.58,21.28 25.43,21.43 25.22,21.43 25.12,21.33 v1(25.12,21.12)
PR9B: length 9.6
  TOP w0.102: v1(25.12,21.92) BGA.G14
  L3_SIGNAL w0.102: 33.82,21.46 25.65,21.46 25.51,21.61 25.22,21.61 25.12,21.71 v1(25.12,21.92)
PR10C: length 11.9
  TOP w0.102: v1(22.72,21.92) BGA.G11
  BOTTOM w0.102: 33.81,22.02 26.38,22.02 26.09,22.32 25.82,22.32 23.12,22.32 v1(22.72,21.92)
PR10D: length 12
  TOP w0.102: v1(22.72,21.12) BGA.H12
  BOTTOM w0.102: 33.81,21.84 26.41,21.84 26.09,21.52 26.04,21.52 23.12,21.52 v1(22.72,21.12)
PR11A: length 7.6
  TOP w0.102: 33.83,21.4 26.87,21.4 26.75,21.52 BGA.G16
PR11B: length 8.5
  TOP w0.102: BGA.H15 25.92,21.12 26.75,21.12 26.85,21.22 33.83,21.22
PR11C: length 11.6
  TOP w0.102: v1(23.52,20.32) BGA.H13
  L4_SIGNAL w0.102: v1(23.52,20.32) BGA.H13 24.49,20.72 25.11,20.1 25.64,20.1 26.29,19.45 33.82,19.45
PR11D: length 12.1
  TOP w0.102: v1(22.72,20.32) BGA.J12
  L4_SIGNAL w0.102: v1(22.72,20.32) BGA.J12 24.73,19.92 25.57,19.92 26.22,19.27 33.82,19.27
PR12A: length 9.3
  TOP w0.102: BGA.H14 25.12,20.32 26.62,20.32 26.73,20.43 33.83,20.43
PR12B: length 7.6
  TOP w0.102: 33.83,20.61 26.75,20.61 26.63,20.72 BGA.H16
PR15A: length 10.2
  TOP w0.102: v1(26.89,19.92) BGA.J16
  L3_SIGNAL w0.102: 33.81,20.68 26.07,20.68 25.73,20.34 25.71,20.21 25.79,20.09 v1(26.89,19.92)
PR15B: length 10.4
  TOP w0.102: v1(24.32,20.32) BGA.J14
  L3_SIGNAL w0.102: 33.81,20.86 26,20.86 25.55,20.41 25.55,20.33 25.53,20.23 25.41,20.15 v1(24.32,20.32)
PR16A: length 8.5
  TOP w0.102: 33.83,19.4 26.73,19.4 26.61,19.52 25.92,19.52 BGA.J15
PR16B: length 7.6
  TOP w0.102: 33.83,19.22 26.71,19.22 26.61,19.12 BGA.K16
PR16C: length 12.7
  TOP w0.102: v1(21.92,21.12) BGA.H11
  BOTTOM w0.102: 33.81,20.5 24.94,20.5 24.72,20.72 BGA.H11 v1(21.92,21.12)
PR16D: length 11.2
  TOP w0.102: v1(23.52,19.52) BGA.J13
  BOTTOM w0.102: 33.81,20.33 25.1,20.33 24.69,19.92 BGA.J13 v1(23.52,19.52)
PR17A: length 10.3
  TOP w0.102: v1(24.32,19.52) BGA.K14
  L3_SIGNAL w0.102: v1(24.32,19.52) 24.75,19.09 33.83,19.09
PR17B: length 9.4
  TOP w0.102: v1(25.12,19.52) BGA.K15
  L3_SIGNAL w0.102: v1(25.12,19.52) 25.45,19.52 25.7,19.27 33.83,19.27
PR17C: length 12
  TOP w0.102: v1(22.72,19.52) BGA.J11
  L4_SIGNAL w0.102: 33.82,18.82 25.04,18.82 24.74,19.12 23.12,19.12 v1(22.72,19.52)
PR17D: length 11.2
  TOP w0.102: v1(23.52,18.72) BGA.L12
  L4_SIGNAL w0.102: 33.82,18.64 25.01,18.64 24.69,18.32 23.92,18.32 v1(23.52,18.72)
PR18A: length 7.6
  TOP w0.102: BGA.L16 26.75,18.32 26.86,18.43 33.83,18.43
PR18B: length 9.3
  TOP w0.102: BGA.L14 25.12,18.72 26.75,18.72 26.86,18.61 33.83,18.61
PR19C: length 10.1
  TOP w0.102: v1(24.32,18.72) BGA.K13
  BOTTOM w0.102: v1(24.32,18.72) 24.57,18.72 24.79,18.94 33.81,18.94
PR19D: length 11.8
  TOP w0.102: v1(22.72,18.72) BGA.K12
  BOTTOM w0.102: v1(22.72,18.72) BGA.K12 33.81,19.12
PR21A: length 8.5
  TOP w0.102: 33.83,17.8 26.87,17.8 26.75,17.92 25.92,17.92 BGA.L15
PR21B: length 7.6
  TOP w0.102: BGA.M16 26.75,17.52 26.85,17.62 33.83,17.62
PR21C: length 14.3
  TOP w0.102: v1(21.92,18.72) BGA.K11
  BOTTOM w0.102: 23.47,6 23.47,15.57 23.12,15.92 23.12,17.29 23.12,18.09 22.89,18.32 22.67,18.32 22.32,18.32 v1(21.92,18.72)
PR21D: length 12.8
  TOP w0.102: v1(23.52,17.92) BGA.L13
  BOTTOM w0.102: 23.64,6 23.64,15.57 23.92,15.85 23.92,17.29 23.92,17.52 v1(23.52,17.92)
PR23A: length 10.3
  TOP w0.102: v1(24.32,17.92) BGA.M14
  L3_SIGNAL w0.102: 33.83,18.39 24.79,18.39 v1(24.32,17.92)
PR23B: length 9.4
  TOP w0.102: v1(25.12,17.92) BGA.M15
  L3_SIGNAL w0.102: 33.83,18.21 25.74,18.21 25.44,17.92 v1(25.12,17.92)
PR23C: length 8.5
  TOP w0.102: BGA.N15 25.92,16.32 26.75,16.32 26.86,16.21 33.83,16.21
PR23D: length 7.6
  TOP w0.102: BGA.P16 26.75,15.92 26.86,16.03 33.83,16.03
PR24A: length 7.6
  TOP w0.102: BGA.N16 26.75,16.72 26.86,16.84 33.83,16.84
PR24B: length 9.3
  TOP w0.102: 33.83,17.01 26.85,17.01 26.75,17.12 25.12,17.12 BGA.N14
PR25C: length 8.5
  TOP w0.102: BGA.P15 25.92,15.52 26.75,15.52 26.85,15.41 33.83,15.41
PR25D: length 7.6
  TOP w0.102: BGA.R16 26.73,15.12 26.84,15.23 33.83,15.23
PT9A: length 11.4
  TOP w0.102: v1(16.32,25.12) BGA.C4
  L3_SIGNAL w0.102: 17.03,35.37 17.03,25.31 16.84,25.12 v1(16.32,25.12)
PT9B: length 11.4
  TOP w0.102: v1(17.92,25.12) BGA.B5
  L3_SIGNAL w0.102: 17.21,35.37 17.21,25.31 17.4,25.12 v1(17.92,25.12)
PT9C: length 10
  TOP w0.102: 15.52,35.36 15.52,25.92 BGA.B3
PT10A: length 9.1
  TOP w0.102: BGA.A4 16.72,26.7 16.94,26.92 16.94,35.36
PT10B: length 10.8
  TOP w0.102: 17.12,35.36 17.12,25.12 BGA.C5
PT11A: length 9.1
  TOP w0.102: 17.64,35.36 17.64,26.87 17.52,26.75 BGA.A5
PT11B: length 10
  TOP w0.102: BGA.B6 17.92,25.92 17.92,26.75 17.82,26.85 17.82,35.36
PT12A: length 9
  TOP w0.102: BGA.A3 15.92,35.36
PT12B: length 10.1
  TOP w0.102: 16.1,35.36 16.1,26.97 16.32,26.75 16.32,25.92 BGA.B4
PT14A: length 11.9
  TOP w0.102: v1(17.92,24.32) BGA.D6
  L4_SIGNAL w0.102: 18.52,35.37 18.52,24.92 v1(17.92,24.32)
PT14B: length 12.8
  TOP w0.102: v1(18.72,23.52) BGA.E7
  L4_SIGNAL w0.102: v1(18.72,23.52) 19.12,23.92 19.12,24.68 18.7,25.1 18.7,35.37
PT14C: length 10.9
  TOP w0.102: 18.61,35.36 18.61,26.86 18.72,26.75 18.72,25.12 BGA.C6
PT14D: length 9.1
  TOP w0.102: BGA.A6 18.32,26.75 18.43,26.86 18.43,35.36
PT15A: length 10.9
  TOP w0.102: v1(19.52,25.12) BGA.B7
  L3_SIGNAL w0.102: v1(19.52,25.12) 19.52,25.51 19.3,25.73 19.3,35.37
PT15B: length 11.8
  TOP w0.102: v1(19.52,24.32) BGA.C7
  L3_SIGNAL w0.102: v1(19.52,24.32) BGA.C7 19.12,35.37
PT16A: length 12.6
  TOP w0.102: v1(17.92,23.52) BGA.E6
  L3_SIGNAL w0.102: v1(17.92,23.52) 18.32,23.92 18.32,24.65 18.43,24.76 18.43,35.37
PT16B: length 11.7
  TOP w0.102: v1(18.72,24.32) BGA.D7
  L3_SIGNAL w0.102: v1(18.72,24.32) 18.72,24.65 18.61,24.76 18.61,35.37
PT17A: length 13.5
  TOP w0.102: v1(19.52,22.72) BGA.F7
  BOTTOM w0.102: v1(19.52,22.72) 19.12,23.12 19.12,25.63 19.44,25.95 19.44,35.37
PT17B: length 12.7
  TOP w0.102: v1(19.52,23.52) BGA.E8
  BOTTOM w0.102: 19.61,35.37 19.61,25.94 19.92,25.64 19.92,23.92 v1(19.52,23.52)
PT17C: length 9.1
  TOP w0.102: 19.23,35.36 19.23,26.85 19.12,26.75 BGA.A7
PT17D: length 10.1
  TOP w0.102: 19.4,35.36 19.4,26.86 19.52,26.75 19.52,25.92 BGA.B8
PT18A: length 10.9
  TOP w0.102: 20.2,35.36 20.2,26.71 20.32,26.59 20.32,25.12 BGA.C8
PT18B: length 9.1
  TOP w0.102: 20.02,35.36 20.02,26.7 19.92,26.6 BGA.A8
PT21A: length 11.7
  TOP w0.102: v1(20.32,24.32) BGA.D8
  L3_SIGNAL w0.102: 20.1,35.37 20.1,24.9 20.32,24.68 v1(20.32,24.32)
PT21B: length 13.4
  TOP w0.102: v1(20.32,22.72) BGA.E9
  L3_SIGNAL w0.102: v1(20.32,22.72) 19.92,23.12 19.92,35.37
PT22A: length 14.2
  TOP w0.102: v1(20.32,21.92) BGA.F8
  L4_SIGNAL w0.102: v1(20.32,21.92) BGA.F8 19.92,24.72 20.01,24.82 20.01,35.36
PT22B: length 12.8
  TOP w0.102: v1(20.32,23.52) BGA.D9
  L4_SIGNAL w0.102: v1(20.32,23.52) BGA.D9 20.72,24.68 20.19,25.21 20.19,35.36
PT22C: length 9.2
  TOP w0.102: v1(20.72,26.89) BGA.A9
  L3_SIGNAL w0.102: v1(20.72,26.89) 20.72,27.33 21.01,27.62 21.01,35.37
PT22D: length 12
  TOP w0.102: v1(21.12,24.32) BGA.C9
  L3_SIGNAL w0.102: v1(21.12,24.32) 20.69,24.75 20.69,26.14 21.19,26.64 21.19,35.37
PT25A: length 10.1
  TOP w0.102: 21.23,35.36 21.23,26.71 21.12,26.6 21.12,25.92 BGA.B9
PT25B: length 9.1
  TOP w0.102: 21.41,35.36 21.41,26.71 21.52,26.6 BGA.A10
PT26A: length 13.5
  TOP w0.102: v1(21.12,22.72) BGA.F9
  L4_SIGNAL w0.102: v1(21.12,22.72) 21.52,23.12 21.52,24.7 21.84,25.03 21.84,35.36
PT26B: length 12.7
  TOP w0.102: v1(22.72,23.52) BGA.E11
  L4_SIGNAL w0.102: 22.02,35.36 22.02,25.02 22.32,24.72 22.32,23.92 v1(22.72,23.52)
PT27A: length 12.7
  TOP w0.102: v1(21.12,23.52) BGA.D10
  BOTTOM w0.102: 21.13,35.37 21.13,25.79 20.72,25.39 20.72,23.92 v1(21.12,23.52)
PT27B: length 12.7
  TOP w0.102: v1(21.92,23.52) BGA.E10
  BOTTOM w0.102: v1(21.92,23.52) 21.52,23.92 21.52,25.56 21.31,25.78 21.31,35.37
PT27C: length 11.8
  TOP w0.102: v1(21.92,24.32) BGA.C10
  L3_SIGNAL w0.102: 21.93,35.36 21.93,25 21.65,24.73 21.65,24.59 v1(21.92,24.32)
PT27D: length 11.7
  TOP w0.102: v1(21.12,25.12) BGA.B10
  L3_SIGNAL w0.102: v1(21.12,25.12) 21.39,24.85 21.53,24.85 21.75,25.08 21.75,35.36
PT28A: length 9.1
  TOP w0.102: 22.22,35.36 22.22,26.85 22.32,26.75 BGA.A11
PT28B: length 10.9
  TOP w0.102: BGA.C11 21.92,25.12 21.92,26.75 22.04,26.86 22.04,35.36
PT32A: length 13.5
  TOP w0.102: v1(21.92,22.72) BGA.F10
  BOTTOM w0.102: 22.62,35.37 22.62,25.9 22.32,25.6 22.32,23.12 v1(21.92,22.72)
PT32B: length 11.9
  TOP w0.102: v1(22.72,24.32) BGA.D11
  BOTTOM w0.102: 22.8,35.37 22.8,25.9 23.12,25.58 23.12,24.72 v1(22.72,24.32)
PT33A: length 10.1
  TOP w0.102: BGA.B11 22.72,25.92 22.72,26.75 22.83,26.86 22.83,35.36
PT33B: length 9.1
  TOP w0.102: BGA.A12 23.12,26.75 23.01,26.85 23.01,35.36
PT34A: length 10.1
  TOP w0.102: 24.43,35.36 24.43,26.86 24.32,26.75 24.32,25.92 BGA.B13
PT34B: length 9.1
  TOP w0.102: 24.61,35.36 24.61,26.85 24.72,26.75 BGA.A14
PT35A: length 11.1
  TOP w0.102: v1(23.52,25.12) BGA.C12
  L3_SIGNAL w0.102: v1(23.52,25.12) 23.31,25.12 23.21,25.22 23.21,25.32 23.21,25.58 23.02,25.77 23.02,35.37
PT35B: length 11.1
  TOP w0.102: v1(22.72,25.12) BGA.B12
  L3_SIGNAL w0.102: 22.84,35.37 22.84,25.69 23.03,25.51 23.03,25.22 22.93,25.12 v1(22.72,25.12)
PT36A: length 10.1
  TOP w0.102: BGA.B14 25.12,25.92 25.12,26.75 25.23,26.86 25.23,35.36
PT36B: length 9.1
  TOP w0.102: 25.41,35.36 25.41,26.86 25.52,26.75 BGA.A15
PT36C: length 10.9
  TOP w0.102: v1(23.52,25.92) BGA.A13
  L4_SIGNAL w0.102: 24.17,35.37 24.17,25.89 23.93,25.65 23.79,25.65 v1(23.52,25.92)
PT36D: length 11
  TOP w0.102: v1(24.32,25.12) BGA.C13
  L4_SIGNAL w0.102: 24.35,35.37 24.35,25.82 24.05,25.53 24.05,25.39 v1(24.32,25.12)

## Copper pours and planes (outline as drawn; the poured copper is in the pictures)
GND on L2_GND: 5.42,5.62 5.42,35.74 34.07,35.74 34.07,5.62
VCC on L5_PWR: 29.54,14.73 29.54,24.79 22.63,24.79 22.63,22.05 22.25,21.67 21.82,21.67 21.56,21.92 21.56,23.72 20.5,24.79 16.71,24.79 16.71,23.88 18.08,23.88 19.94,22.02 19.94,20.9 20.07,20.78 20.8,20.78 21.69,19.89 21.95,19.89 22.3,19.53 22.3,18.32 21.72,18.32 20.68,19.36 20.68,19.76 20.55,19.89 20.14,19.89 19.86,19.61 19.86,19.43 19.66,19.23 19.11,19.23 19.07,19.27 19.07,21.42 18.9,21.59 16.79,21.59 16.79,23.14 5.77,23.14 5.77,35.43 33.88,35.43 33.88,5.99 5.77,5.99 5.77,14.73
VCCIO0 on L5_PWR: 20.65,20.88 20.12,20.88 20.07,20.93 20.07,22.1 18.14,24.03 16.87,24.03 16.87,24.66 20.45,24.66 21.44,23.67 21.44,21.87 21.77,21.54 22.33,21.54 22.76,21.97 22.76,24.66 23.85,24.66 23.85,21.31 23.44,20.9 21.97,20.9 21.29,21.59 20.98,21.59 20.65,21.26
VCCIO1 on L5_PWR: 23.98,24.66 23.98,21.23 23.55,20.8 21.89,20.8 21.23,21.46 21.03,21.46 20.78,21.21 20.78,20.96 21.74,19.99 22,19.99 22.4,19.58 22.4,18.31 23.93,16.79 29.44,16.79 29.44,24.66
VCCIO2 on L5_PWR: 5.77,14.86 5.77,17.32 16.87,17.32 16.87,19.13 19.71,19.13 19.96,19.38 19.96,19.56 20.17,19.76 20.52,19.76 20.57,19.71 20.57,19.3 21.66,18.22 22.32,18.22 23.88,16.66 29.44,16.66 29.44,14.86
VCCIO3 on L5_PWR: 16.77,19.13 16.77,17.42 5.77,17.42 5.77,19.13
VCCIO4 on L5_PWR: 5.77,21.46 18.85,21.46 18.97,21.34 18.97,19.23 5.77,19.23
VCCIO5 on L5_PWR: 16.69,23.04 16.69,21.59 5.77,21.59 5.77,23.04

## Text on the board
User.Comments: RCI | RP | 08/06/14 | DWG NO: | XO3L-69E-400caBGA | REVISION | 1.0 | SHEET | 1 | OF | XO3L-69E-400CABGA PCB BREAKOUT | LATTICE SEMICONDUCTOR CORPORATION
Ref Des/Silkscreen Top: PCB BREAKOUT | XO3L-69E-400CABGA | SEMICONDUCTOR | LATTICE | A | B | C | D | E | F | G | H | J | K | L | M | N | P | R | T | 1 | 2 | 3 | 4 | 5 | 6 | 7 | 8 | 9 | 10 | 11 | 12 | 13 | 14 | 15 | 16
PAGE_OUTLINE: 1 | INITIAL RELEASE | MM/DD/YYYY | XXXX XXXXX | SPECIAL INSTRUCTIONS: | 1/2 CU OZ FOR INTERNAL AND EXTERNAL LAYERS | MIN BOARD THICKNESS IS 62MILS. | DESIGNED BY: | APPROVED BY: | SIGNATURES         DATE | REV | DESCRIPTION | ESCAPE VIA DRILL | TRACE WIDTH/SPACE | ESCAPE VIA PAD | ARRAY SIZE | BGA LAND OPENING | BGA LAND PAD | PACKAGE SIZE | PITCH | SIGNAL         (L4) | SIGNAL         (L3) | GND     PLANE  (L2) | POWER   PLANE  (L5) | PRIMARY SIDE   (L1) | SECONDARY SIDE (L6) | SECONDARY SILKSCREEN | SECONDARY SOLDERMASK | PRIMARY SOLDERMASK | PRIMARY SILKSCREEN | 0.10/0.08 | 14 x 14 | 16 x 16 | 0.3048 | 0.1524 | 0.4318 | 0.3556 | 0.8 | MM | DATE | 551.18 x 551.18 | 629.92 x 629.92 | 4/3 | 12 | 31.5 | 6 | 14 | 17 | MILS | APPROVED | PCB BREAKOUT DETAILS | 6 LAYER STACKUP | REVISION
BODY_CENTER: FIGURE | SIZE | 10.0 | ALL UNITS ARE IN MILS | SIZE MM | 0.254 | PLATED | QTY | 83 | DRILL CHART: TOP to L4_SIGNAL
PLACE_BOUND_TOP: FIGURE | SIZE | 10.0 | ALL UNITS ARE IN MILS | SIZE MM | 0.254 | PLATED | QTY | 116 | DRILL CHART: TOP to L3_SIGNAL
DISPLAY_TOP: FIGURE | SIZE | 10.0 | ALL UNITS ARE IN MILS | SIZE MM | 0.254 | PLATED | QTY | 50 | DRILL CHART: TOP to BOTTOM
